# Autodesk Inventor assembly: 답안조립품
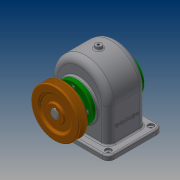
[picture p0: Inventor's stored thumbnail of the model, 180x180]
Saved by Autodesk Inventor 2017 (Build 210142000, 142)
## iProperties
Part Number: 답안조립품
Material: 일반
Document SubType Name: Assembly
Designer: 20
Author: 20
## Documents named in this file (14)
- C:\Users\20\Desktop\480310V1010\답안조립품.iam
- C:\Users\20\Desktop\480310V1010\본체.ipt
- C:\Users\20\Desktop\480310V1010\축.ipt
- C:\Users\20\Desktop\480310V1010\베어링 6203.ipt
- C:\Users\20\Desktop\480310V1010\키 6x6x22.ipt
- C:\Users\20\Desktop\480310V1010\키 5x5x18.ipt
- C:\Users\20\Desktop\480310V1010\스퍼기어.ipt
- C:\Users\20\Desktop\480310V1010\부시.ipt
- C:\Users\20\Desktop\480310V1010\앞커버.ipt
- C:\Users\20\Desktop\480310V1010\뒤커버.ipt
- C:\Users\20\Desktop\480310V1010\V-벨트풀리.ipt
- C:\Users\20\Desktop\480310V1010\멈춤나사 M4.ipt
- C:\Users\20\Desktop\480310V1010\오일 실 28 40 8.ipt
- C:\Users\20\Desktop\480310V1010\볼트 M4.ipt
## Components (1 placed, 1 different names)
1. V-벨트풀리:1
